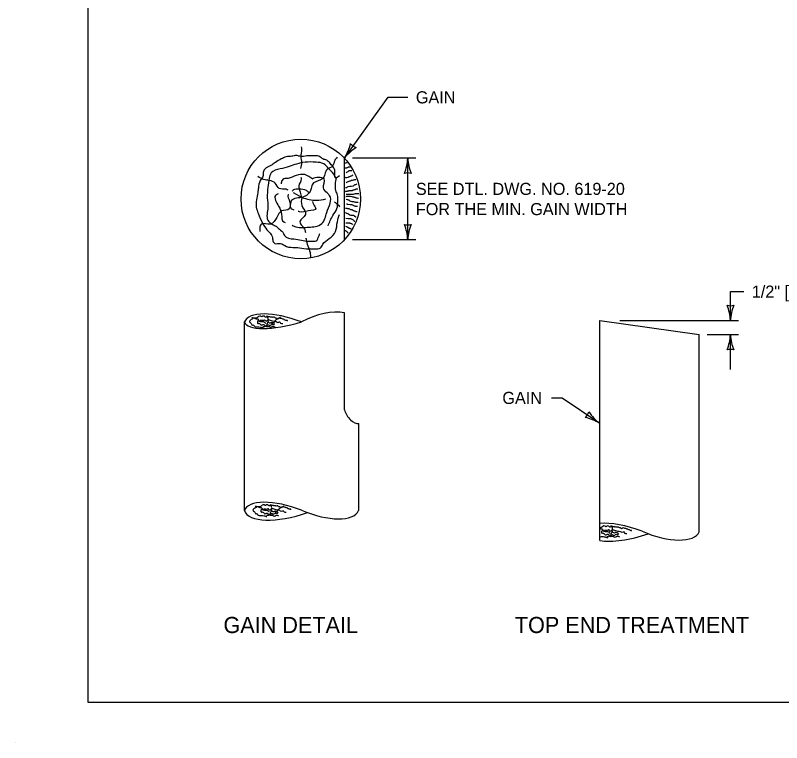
# Model space of a CAD drawing. Extents: x 49991.4 to 50021, y 49987.6 to 50011.4.
# Drawn here: x 49999.977 to 50003.769, y 49999.862 to 50003.463 of the extents above; entities that cross this region are included whole.
import ezdxf

# ---------------------------------------------------------------- set-up
doc = ezdxf.new("R2010")
doc.units = 0
for name, color, linetype in [('Level 1', 7, 'Continuous'), ('Level 2', 7, 'Continuous'), ('Level 3', 7, 'Continuous')]:
    doc.layers.add(name, color=color, linetype=linetype)

msp = doc.modelspace()

# ---------------------------------------------------------------- linework, layer by layer
at = {"layer": 'Level 1'}
for p, q in [((50001.605, 50002.3516), (50001.605, 50002.7561)), ((50001.3944, 50002.561), (50001.3536, 50002.5837)), ((50001.605, 50001.5105), (50001.605, 50001.9906)), ((50002.8687, 50001.9517), (50003.3612, 50001.8825)), ((50002.8687, 50000.8627), (50002.8687, 50001.9517)), ((50001.1101, 50001.011), (50001.1101, 50001.9454)), ((50003.3612, 50000.9062), (50003.3612, 50001.8825)), ((50001.6764, 50001.011), (50001.6764, 50001.4416)), ((49999.9766, 49999.8624), (49999.9766, 49999.8624))]:
    msp.add_line(p, q, dxfattribs=at)
msp.add_lwpolyline([(50008.6146, 50011.2628), (50000.3356, 50011.2628), (50000.3356, 50000.0624), (50008.6146, 50000.0624)], close=True, dxfattribs=at)
for points in [[(50001.6071, 50002.7316), (50001.6092, 50002.7327), (50001.6124, 50002.7327), (50001.6167, 50002.7337), (50001.6188, 50002.7337)], [(50001.6103, 50002.7092), (50001.6113, 50002.7071), (50001.6135, 50002.7081), (50001.6167, 50002.7081), (50001.6188, 50002.7092), (50001.621, 50002.7092), (50001.6231, 50002.7113), (50001.6253, 50002.7124), (50001.6295, 50002.7135), (50001.6338, 50002.7135)], [(50001.6092, 50002.6612), (50001.6113, 50002.6601), (50001.6135, 50002.6601), (50001.6178, 50002.6601), (50001.6231, 50002.6612), (50001.6263, 50002.6633), (50001.6285, 50002.6644), (50001.6306, 50002.6655), (50001.6328, 50002.6655), (50001.6349, 50002.6665), (50001.6381, 50002.6676), (50001.6403, 50002.6687), (50001.6435, 50002.6697), (50001.6445, 50002.6719), (50001.6478, 50002.674)], [(50001.6135, 50002.6836), (50001.6167, 50002.6868), (50001.6199, 50002.6889), (50001.6231, 50002.69), (50001.6253, 50002.6911), (50001.6274, 50002.6932), (50001.6295, 50002.6953), (50001.6328, 50002.6953), (50001.6349, 50002.6953), (50001.637, 50002.6953), (50001.6392, 50002.6953), (50001.6413, 50002.6953)], [(50001.6135, 50002.6345), (50001.6178, 50002.6377), (50001.6199, 50002.6388), (50001.6242, 50002.6409), (50001.6295, 50002.642), (50001.6317, 50002.6431), (50001.6349, 50002.6441), (50001.6381, 50002.6452), (50001.6403, 50002.6463), (50001.6435, 50002.6463), (50001.6456, 50002.6473), (50001.651, 50002.6484), (50001.6542, 50002.6484), (50001.6574, 50002.6495), (50001.6617, 50002.6495)], [(50001.6081, 50002.5919), (50001.6092, 50002.5897), (50001.6103, 50002.5919), (50001.6124, 50002.5929), (50001.6199, 50002.5929), (50001.622, 50002.594), (50001.6242, 50002.594), (50001.6263, 50002.594), (50001.6285, 50002.5951), (50001.6306, 50002.5951), (50001.6328, 50002.5951), (50001.6349, 50002.5951), (50001.637, 50002.5951), (50001.6403, 50002.5951), (50001.6445, 50002.5961), (50001.6467, 50002.5972), (50001.6488, 50002.5983), (50001.6542, 50002.5993), (50001.6563, 50002.6004), (50001.6585, 50002.6015), (50001.6638, 50002.6036), (50001.667, 50002.6047), (50001.6692, 50002.6047), (50001.6713, 50002.6047)], [(50001.6103, 50002.61), (50001.6167, 50002.6111), (50001.6188, 50002.6121), (50001.621, 50002.6143), (50001.6231, 50002.6153), (50001.6317, 50002.6164), (50001.6349, 50002.6175), (50001.637, 50002.6175), (50001.6392, 50002.6175), (50001.6478, 50002.6185), (50001.6499, 50002.6196), (50001.6531, 50002.6228), (50001.6552, 50002.6239), (50001.6585, 50002.6249), (50001.6617, 50002.626), (50001.6649, 50002.6271), (50001.666, 50002.6292)], [(50001.6124, 50002.5663), (50001.6146, 50002.5663), (50001.6167, 50002.5673), (50001.6231, 50002.5673), (50001.6263, 50002.5673), (50001.6285, 50002.5684), (50001.6317, 50002.5684), (50001.6338, 50002.5684), (50001.6424, 50002.5663), (50001.6456, 50002.5652), (50001.6478, 50002.5641), (50001.651, 50002.5641), (50001.6542, 50002.5631), (50001.6563, 50002.562), (50001.6595, 50002.5609), (50001.6617, 50002.5599), (50001.6638, 50002.5599), (50001.667, 50002.5588), (50001.6713, 50002.5577), (50001.6745, 50002.5577)], [(50001.6135, 50002.5769), (50001.6167, 50002.5769), (50001.6188, 50002.5769), (50001.6242, 50002.5769), (50001.6263, 50002.5769), (50001.6317, 50002.5769), (50001.636, 50002.5769), (50001.6381, 50002.5769), (50001.6413, 50002.5769), (50001.6435, 50002.5769), (50001.6456, 50002.5769), (50001.6499, 50002.578), (50001.6606, 50002.5801), (50001.6649, 50002.5801), (50001.6692, 50002.5801), (50001.6713, 50002.5801), (50001.6735, 50002.5801), (50001.6767, 50002.5801)], [(50001.6135, 50002.5535), (50001.6199, 50002.5513), (50001.622, 50002.5503), (50001.6274, 50002.5492), (50001.6295, 50002.5471), (50001.6328, 50002.5449), (50001.637, 50002.5428), (50001.6413, 50002.5417), (50001.6488, 50002.5407), (50001.651, 50002.5407), (50001.6531, 50002.5396), (50001.6552, 50002.5396), (50001.6574, 50002.5396), (50001.6606, 50002.5385), (50001.6649, 50002.5385), (50001.6681, 50002.5385), (50001.6735, 50002.5385)], [(50001.6167, 50002.5321), (50001.6178, 50002.5289), (50001.6199, 50002.5289), (50001.6338, 50002.5268), (50001.6403, 50002.5257), (50001.6435, 50002.5247), (50001.6456, 50002.5247), (50001.6478, 50002.5236), (50001.651, 50002.5215), (50001.6542, 50002.5193), (50001.6574, 50002.5193), (50001.6595, 50002.5183), (50001.6627, 50002.5183), (50001.667, 50002.5183), (50001.6692, 50002.5183)], [(50001.6092, 50002.4863), (50001.6135, 50002.4852), (50001.6156, 50002.4841), (50001.6178, 50002.4841), (50001.622, 50002.482), (50001.6263, 50002.4788), (50001.6295, 50002.4767), (50001.6306, 50002.4745), (50001.6328, 50002.4745), (50001.637, 50002.4735), (50001.6392, 50002.4735), (50001.6413, 50002.4735), (50001.6456, 50002.4735), (50001.6478, 50002.4735), (50001.652, 50002.4724), (50001.6542, 50002.4713), (50001.6542, 50002.4692), (50001.6563, 50002.4681), (50001.6606, 50002.466), (50001.6627, 50002.466)], [(50001.6103, 50002.5087), (50001.6146, 50002.5076), (50001.6178, 50002.5076), (50001.6199, 50002.5065), (50001.6263, 50002.5065), (50001.6306, 50002.5044), (50001.6328, 50002.5033), (50001.6349, 50002.5023), (50001.6424, 50002.5012), (50001.6456, 50002.5001), (50001.651, 50002.4969), (50001.6531, 50002.4959), (50001.6563, 50002.4948), (50001.6595, 50002.4937), (50001.6617, 50002.4916), (50001.6649, 50002.4916), (50001.6681, 50002.4916)], [(50001.6124, 50002.4596), (50001.6253, 50002.4575), (50001.6285, 50002.4575), (50001.6349, 50002.4575), (50001.637, 50002.4564), (50001.6392, 50002.4553), (50001.6413, 50002.4543), (50001.6435, 50002.4532), (50001.6456, 50002.4521), (50001.6478, 50002.45), (50001.651, 50002.4489), (50001.652, 50002.4468), (50001.6542, 50002.4447), (50001.6563, 50002.4436)], [(50001.6113, 50002.4191), (50001.6135, 50002.4169), (50001.6167, 50002.4169), (50001.621, 50002.4148), (50001.6231, 50002.4148), (50001.6242, 50002.4127), (50001.6253, 50002.4105), (50001.6274, 50002.4105), (50001.6295, 50002.4095), (50001.6328, 50002.4095), (50001.6349, 50002.4084), (50001.637, 50002.4084), (50001.6381, 50002.4041)], [(50001.6124, 50002.4361), (50001.6146, 50002.4351), (50001.6274, 50002.4351), (50001.6306, 50002.4351), (50001.6328, 50002.434), (50001.6349, 50002.434), (50001.6403, 50002.4329), (50001.6445, 50002.4297), (50001.6456, 50002.4276)], [(50001.6092, 50002.3999), (50001.6092, 50002.3977), (50001.6124, 50002.3956), (50001.6146, 50002.3945), (50001.6167, 50002.3924), (50001.6188, 50002.3903), (50001.621, 50002.3892), (50001.621, 50002.3871), (50001.6242, 50002.3849)]]:
    msp.add_lwpolyline(points, dxfattribs=at)
msp.add_circle((50001.3894, 50002.5538), 0.2956, dxfattribs=at)
for centre, major_axis, ratio, start_param, end_param in [((50001.4558, 50001.8277), (0.2192, 0.1177), 0.537084, 0.577032, 1.570796), ((50001.3557, 50001.8503), (-0.2457, 0.0951), 0.387082, 4.712389, 6.283185), ((50001.3686, 50002.0242), (-0.2585, -0.0788), 0.304673, 0, 1.570796), ((50001.6514, 50001.5052), (0.036, -0.0602), 0.577668, 4.296437, 6.00385), ((50001.3566, 50000.918), (-0.2457, 0.0951), 0.387082, 4.712389, 6.306248), ((50001.3866, 50001.1087), (-0.2766, -0.0977), 0.384401, 0, 1.563046), ((50001.4354, 50001.1146), (0.2396, -0.1036), 0.420526, 4.719014, 6.283185), ((50003.0413, 50000.8139), (-0.2457, 0.0951), 0.387082, 4.71239, 5.629208), ((50003.0729, 50001.0039), (-0.2766, -0.0977), 0.384401, 0.614947, 1.563386), ((50003.1217, 50001.0098), (0.2396, -0.1036), 0.420526, 4.712389, 6.283185)]:
    msp.add_ellipse(centre, major_axis=major_axis, ratio=ratio, start_param=start_param, end_param=end_param, dxfattribs=at)
for points in [[(50001.3893, 50002.7052), (50001.3944, 50002.7344), (50001.3912, 50002.7628), (50001.3944, 50002.7992), (50001.3928, 50002.8111)], [(50001.5477, 50002.7153), (50001.5324, 50002.7322), (50001.5175, 50002.7459), (50001.4992, 50002.7517), (50001.4842, 50002.7625), (50001.4721, 50002.7668), (50001.4466, 50002.7668), (50001.4194, 50002.7668), (50001.3849, 50002.7651), (50001.3665, 50002.7698), (50001.3454, 50002.7651), (50001.3168, 50002.7625), (50001.2926, 50002.7517), (50001.264, 50002.7351), (50001.2475, 50002.723), (50001.211, 50002.702), (50001.2038, 50002.6856), (50001.202, 50002.6656), (50001.1883, 50002.6445), (50001.1794, 50002.607), (50001.1764, 50002.5857), (50001.169, 50002.5135), (50001.1781, 50002.4832), (50001.2004, 50002.4334), (50001.2218, 50002.4015), (50001.2488, 50002.3653), (50001.2518, 50002.346), (50001.2609, 50002.3338), (50001.2882, 50002.3338), (50001.3184, 50002.3187), (50001.362, 50002.3142), (50001.4043, 50002.3082), (50001.4584, 50002.3067), (50001.4856, 50002.311), (50001.4992, 50002.3306), (50001.5295, 50002.358), (50001.5613, 50002.3926), (50001.5703, 50002.441), (50001.5815, 50002.4767)], [(50001.5692, 50002.76), (50001.5571, 50002.7447), (50001.5466, 50002.7162), (50001.5194, 50002.6996), (50001.5087, 50002.677), (50001.494, 50002.6514), (50001.4877, 50002.6484), (50001.4455, 50002.6244), (50001.4395, 50002.6), (50001.4169, 50002.5713), (50001.3944, 50002.561)], [(50001.5661, 50002.6528), (50001.5526, 50002.677), (50001.5271, 50002.7054), (50001.5028, 50002.7282), (50001.4649, 50002.7358), (50001.4109, 50002.7358), (50001.3687, 50002.7268), (50001.3323, 50002.7145), (50001.287, 50002.7027), (50001.2432, 50002.6829), (50001.2328, 50002.6557), (50001.2265, 50002.6121), (50001.2236, 50002.5592), (50001.2265, 50002.511), (50001.2265, 50002.4489), (50001.245, 50002.4309), (50001.2631, 50002.4205), (50001.2841, 50002.404), (50001.3036, 50002.3827), (50001.3082, 50002.3722), (50001.355, 50002.3557), (50001.3928, 50002.3494), (50001.4258, 50002.345), (50001.4468, 50002.345), (50001.4649, 50002.3467), (50001.4786, 50002.3694), (50001.4836, 50002.383)], [(50001.5815, 50002.6685), (50001.5597, 50002.6582), (50001.5582, 50002.6959), (50001.546, 50002.7171)], [(50001.4484, 50002.6514), (50001.4092, 50002.6742), (50001.3672, 50002.6708), (50001.3263, 50002.6557), (50001.3051, 50002.6528), (50001.2931, 50002.6362), (50001.2926, 50002.6288)], [(50001.3272, 50002.5969), (50001.3172, 50002.6016), (50001.2824, 50002.606), (50001.2631, 50002.6316), (50001.2342, 50002.6452), (50001.2056, 50002.6497), (50001.1769, 50002.6649)], [(50001.3466, 50002.4234), (50001.3653, 50002.4158), (50001.4289, 50002.4144), (50001.462, 50002.4177), (50001.494, 50002.4325), (50001.518, 50002.487), (50001.5314, 50002.5713), (50001.5194, 50002.5834), (50001.5012, 50002.6091), (50001.5043, 50002.6528), (50001.4774, 50002.6605), (50001.4468, 50002.6542)], [(50001.3944, 50002.561), (50001.3881, 50002.588), (50001.3806, 50002.6194), (50001.3928, 50002.6528), (50001.3915, 50002.6598)], [(50001.5246, 50002.4207), (50001.548, 50002.4717), (50001.5678, 50002.5063), (50001.5724, 50002.5443), (50001.5708, 50002.5728), (50001.5633, 50002.5956), (50001.5661, 50002.6589)], [(50001.3471, 50002.5926), (50001.355, 50002.6), (50001.3806, 50002.6044), (50001.4152, 50002.597), (50001.4302, 50002.5863)], [(50001.3944, 50002.561), (50001.34, 50002.5396), (50001.3323, 50002.505), (50001.2946, 50002.4944), (50001.2704, 50002.4627), (50001.2388, 50002.4296), (50001.1937, 50002.4296), (50001.1859, 50002.3934)], [(50001.2774, 50002.58), (50001.2644, 50002.5713), (50001.2796, 50002.5186), (50001.2946, 50002.4777), (50001.3051, 50002.44), (50001.3119, 50002.4375)], [(50001.3566, 50002.4992), (50001.3444, 50002.5035), (50001.337, 50002.5368), (50001.3293, 50002.5758), (50001.33, 50002.5767)], [(50001.3944, 50002.561), (50001.3944, 50002.5215), (50001.4122, 50002.4763), (50001.3854, 50002.4415), (50001.4109, 50002.3978), (50001.4119, 50002.3875)], [(50001.3944, 50002.561), (50001.4682, 50002.5472), (50001.5132, 50002.5542)], [(50001.4476, 50002.5414), (50001.4516, 50002.5275), (50001.4637, 50002.5063), (50001.4275, 50002.4944), (50001.3836, 50002.4898), (50001.3764, 50002.4925)], [(50001.5568, 50002.5395), (50001.5753, 50002.523), (50001.5815, 50002.5143)], [(50001.4148, 50002.3605), (50001.4152, 50002.3557), (50001.4244, 50002.3226), (50001.435, 50002.2892), (50001.4377, 50002.2622)], [(50001.3229, 50001.9486), (50001.3229, 50001.9516), (50001.3171, 50001.9516), (50001.3128, 50001.9544), (50001.3085, 50001.9544), (50001.3042, 50001.9588), (50001.2998, 50001.9588), (50001.294, 50001.9616), (50001.2897, 50001.9616), (50001.2811, 50001.9645), (50001.2724, 50001.9602), (50001.2681, 50001.9645), (50001.2624, 50001.9645), (50001.258, 50001.9688), (50001.2508, 50001.9674), (50001.2465, 50001.9688), (50001.2421, 50001.9688), (50001.2364, 50001.9703), (50001.2321, 50001.9703), (50001.2263, 50001.9717), (50001.2191, 50001.9717), (50001.2191, 50001.9688), (50001.2148, 50001.9688), (50001.209, 50001.9731), (50001.2004, 50001.9731), (50001.196, 50001.9703), (50001.1917, 50001.9731), (50001.1802, 50001.9717), (50001.1701, 50001.9645), (50001.1586, 50001.9645), (50001.1528, 50001.9631), (50001.1485, 50001.9588), (50001.1398, 50001.9544), (50001.1355, 50001.9472), (50001.1369, 50001.9443), (50001.1441, 50001.9371), (50001.1499, 50001.9285), (50001.1528, 50001.9313), (50001.1586, 50001.9256), (50001.1658, 50001.9213), (50001.1744, 50001.9213), (50001.1903, 50001.9198), (50001.2046, 50001.9155)], [(50001.2162, 50001.9371), (50001.2104, 50001.9429), (50001.1989, 50001.9458), (50001.1859, 50001.9472), (50001.1773, 50001.9588), (50001.1715, 50001.9588), (50001.1672, 50001.9602), (50001.1571, 50001.9645), (50001.147, 50001.966)], [(50001.2998, 50001.9357), (50001.2912, 50001.9371), (50001.2854, 50001.9443), (50001.2767, 50001.9415), (50001.2681, 50001.9458), (50001.2552, 50001.9472), (50001.245, 50001.9501), (50001.2249, 50001.9516), (50001.2162, 50001.9472), (50001.2119, 50001.9544), (50001.2061, 50001.953), (50001.1975, 50001.9516), (50001.1888, 50001.9516), (50001.1874, 50001.9472), (50001.1816, 50001.9501), (50001.1773, 50001.9501), (50001.1744, 50001.9415), (50001.1773, 50001.9371), (50001.1816, 50001.9386), (50001.1874, 50001.9357), (50001.1931, 50001.9299), (50001.2061, 50001.9328), (50001.2148, 50001.9242), (50001.2263, 50001.9227), (50001.2321, 50001.9227), (50001.2407, 50001.9184), (50001.2494, 50001.9227), (50001.2624, 50001.9198)], [(50001.2306, 50001.9429), (50001.2263, 50001.953), (50001.2291, 50001.9602), (50001.2249, 50001.9688), (50001.222, 50001.9761)], [(50001.245, 50001.9371), (50001.2624, 50001.9501), (50001.2681, 50001.9573), (50001.2825, 50001.9645), (50001.2883, 50001.9703)], [(50001.2205, 50001.927), (50001.2104, 50001.9213), (50001.2018, 50001.9213)], [(50001.2566, 50001.9386), (50001.2508, 50001.94), (50001.2407, 50001.9415), (50001.2379, 50001.9386), (50001.2321, 50001.9415), (50001.2249, 50001.9415), (50001.222, 50001.927), (50001.2277, 50001.9313), (50001.2321, 50001.9285), (50001.2393, 50001.9285), (50001.2465, 50001.9328), (50001.2552, 50001.9313), (50001.258, 50001.9343), (50001.2594, 50001.9371)], [(50001.3402, 50001.0146), (50001.3402, 50001.0175), (50001.3344, 50001.0175), (50001.3302, 50001.0204), (50001.3258, 50001.0204), (50001.3215, 50001.0247), (50001.3172, 50001.0247), (50001.3114, 50001.0276), (50001.3071, 50001.0276), (50001.2984, 50001.0304), (50001.2898, 50001.0261), (50001.2854, 50001.0304), (50001.2797, 50001.0304), (50001.2754, 50001.0348), (50001.2681, 50001.0334), (50001.2639, 50001.0348), (50001.2595, 50001.0348), (50001.2537, 50001.0362), (50001.2494, 50001.0362), (50001.2436, 50001.0376), (50001.2364, 50001.0376), (50001.2364, 50001.0348), (50001.2321, 50001.0348), (50001.2264, 50001.0391), (50001.2177, 50001.0391), (50001.2134, 50001.0362), (50001.2091, 50001.0391), (50001.1976, 50001.0376), (50001.1874, 50001.0304), (50001.1759, 50001.0304), (50001.1701, 50001.029), (50001.1658, 50001.0247), (50001.1572, 50001.0204), (50001.1528, 50001.0131), (50001.1543, 50001.0103), (50001.1615, 50001.0031), (50001.1673, 50000.9944), (50001.1701, 50000.9973), (50001.1759, 50000.9916), (50001.1831, 50000.9872), (50001.1918, 50000.9872), (50001.2076, 50000.9858), (50001.222, 50000.9814)], [(50001.248, 50001.0089), (50001.2436, 50001.0189), (50001.2465, 50001.0261), (50001.2422, 50001.0348), (50001.2394, 50001.042)], [(50001.2336, 50001.0031), (50001.2278, 50001.0089), (50001.2163, 50001.0117), (50001.2033, 50001.0131), (50001.1946, 50001.0247), (50001.1888, 50001.0247), (50001.1846, 50001.0261), (50001.1745, 50001.0304), (50001.1643, 50001.0319)], [(50001.3172, 50001.0016), (50001.3085, 50001.0031), (50001.3027, 50001.0103), (50001.2941, 50001.0074), (50001.2854, 50001.0117), (50001.2725, 50001.0131), (50001.2624, 50001.0161), (50001.2422, 50001.0175), (50001.2336, 50001.0131), (50001.2292, 50001.0204), (50001.2235, 50001.0189), (50001.2148, 50001.0175), (50001.2062, 50001.0175), (50001.2047, 50001.0131), (50001.199, 50001.0161), (50001.1946, 50001.0161), (50001.1918, 50001.0074), (50001.1946, 50001.0031), (50001.199, 50001.0045), (50001.2047, 50001.0016), (50001.2105, 50000.9959), (50001.2235, 50000.9988), (50001.2321, 50000.9901), (50001.2436, 50000.9886), (50001.2494, 50000.9886), (50001.2581, 50000.9843), (50001.2667, 50000.9886), (50001.2797, 50000.9858)], [(50001.2739, 50001.0045), (50001.2681, 50001.0059), (50001.2581, 50001.0074), (50001.2552, 50001.0045), (50001.2494, 50001.0074), (50001.2422, 50001.0074), (50001.2394, 50000.993), (50001.2451, 50000.9973), (50001.2494, 50000.9944), (50001.2566, 50000.9944), (50001.2639, 50000.9988), (50001.2725, 50000.9973), (50001.2754, 50001.0002), (50001.2768, 50001.0031)], [(50001.2624, 50001.0031), (50001.2797, 50001.0161), (50001.2854, 50001.0233), (50001.2999, 50001.0304), (50001.3057, 50001.0362)], [(50001.2379, 50000.993), (50001.2278, 50000.9872), (50001.2191, 50000.9872)], [(50003.0265, 50000.9098), (50003.0265, 50000.9127), (50003.0207, 50000.9127), (50003.0164, 50000.9156), (50003.0121, 50000.9156), (50003.0078, 50000.9199), (50003.0034, 50000.9199), (50002.9976, 50000.9228), (50002.9933, 50000.9228), (50002.9847, 50000.9257), (50002.9761, 50000.9214), (50002.9717, 50000.9257), (50002.966, 50000.9257), (50002.9616, 50000.93), (50002.9544, 50000.9286), (50002.9501, 50000.93), (50002.9458, 50000.93), (50002.94, 50000.9314), (50002.9357, 50000.9314), (50002.9299, 50000.9329), (50002.9227, 50000.9329), (50002.9227, 50000.93), (50002.9184, 50000.93), (50002.9126, 50000.9343), (50002.904, 50000.9343), (50002.8996, 50000.9314), (50002.8953, 50000.9343), (50002.8838, 50000.9329), (50002.8737, 50000.9257), (50002.8687, 50000.9257)], [(50002.9343, 50000.9041), (50002.9299, 50000.9142), (50002.9328, 50000.9214), (50002.9285, 50000.93), (50002.9256, 50000.9372)], [(50002.9198, 50000.8983), (50002.914, 50000.9041), (50002.9025, 50000.9069), (50002.8895, 50000.9084), (50002.8809, 50000.9199), (50002.8751, 50000.9199), (50002.8708, 50000.9214), (50002.8687, 50000.9222)], [(50003.0034, 50000.8969), (50002.9948, 50000.8983), (50002.989, 50000.9055), (50002.9803, 50000.9027), (50002.9717, 50000.9069), (50002.9588, 50000.9084), (50002.9486, 50000.9113), (50002.9285, 50000.9127), (50002.9198, 50000.9084), (50002.9155, 50000.9156), (50002.9098, 50000.9142), (50002.9011, 50000.9127), (50002.8925, 50000.9127), (50002.891, 50000.9084), (50002.8853, 50000.9113), (50002.8809, 50000.9113), (50002.878, 50000.9027), (50002.8809, 50000.8983), (50002.8853, 50000.8997), (50002.891, 50000.8969), (50002.8968, 50000.8911), (50002.9098, 50000.894), (50002.9184, 50000.8854), (50002.9299, 50000.8839), (50002.9357, 50000.8839), (50002.9443, 50000.8796), (50002.953, 50000.8839), (50002.966, 50000.881)], [(50002.9241, 50000.8882), (50002.914, 50000.8824), (50002.9054, 50000.8824)], [(50002.9602, 50000.8997), (50002.9544, 50000.9012), (50002.9443, 50000.9027), (50002.9415, 50000.8997), (50002.9357, 50000.9027), (50002.9285, 50000.9027), (50002.9256, 50000.8882), (50002.9313, 50000.8925), (50002.9357, 50000.8897), (50002.9429, 50000.8897), (50002.9501, 50000.894), (50002.9588, 50000.8925), (50002.9616, 50000.8954), (50002.9631, 50000.8983)], [(50002.8687, 50000.8828), (50002.8694, 50000.8824), (50002.878, 50000.8824), (50002.8939, 50000.881), (50002.9083, 50000.8767)]]:
    msp.add_spline(points, degree=3, dxfattribs=at)
at = {"layer": 'Level 3'}
for p, q in [((50001.605, 50002.7561), (50001.8223, 50003.057)), ((50001.8223, 50003.057), (50001.9187, 50003.057)), ((50001.9587, 50002.7561), (50001.645, 50002.7561)), ((50001.9187, 50002.3516), (50001.9187, 50002.7561)), ((50001.9587, 50002.3516), (50001.645, 50002.3516)), ((50003.5156, 50001.9517), (50003.5156, 50002.0951)), ((50003.5156, 50002.0951), (50003.5813, 50002.0951)), ((50002.9687, 50001.9517), (50003.5556, 50001.9517)), ((50003.4012, 50001.8825), (50003.5556, 50001.8825)), ((50003.5156, 50001.7091), (50003.5156, 50001.8825)), ((50002.6299, 50001.569), (50002.6837, 50001.569)), ((50002.6837, 50001.569), (50002.8687, 50001.4435))]:
    msp.add_line(p, q, dxfattribs=at)
for centre, radius, start, end in [((50001.4195, 50002.8787), 0.2223, 326.5292, 346.7127), ((50001.6801, 50002.86), 0.0548, 216.3076, 252.0299), ((50001.7869, 50002.6105), 0.233, 122.0916, 141.3414), ((50001.686, 50002.7676), 0.233, 337.9228, 357.1727), ((50002.1408, 50002.7652), 0.2223, 182.3605, 202.544), ((50001.9187, 50002.6279), 0.0548, 72.1388, 107.8612), ((50001.6966, 50002.3424), 0.2223, 2.3605, 22.544), ((50001.9187, 50002.4798), 0.0548, 252.1388, 287.8612), ((50002.1514, 50002.3401), 0.233, 157.9228, 177.1727), ((50003.5156, 50002.0799), 0.0548, 252.1388, 287.8612), ((50003.2829, 50001.9402), 0.233, 2.8273, 22.0772), ((50003.7377, 50001.9425), 0.2223, 157.456, 177.6395), ((50003.2935, 50001.8917), 0.2223, 337.456, 357.6395), ((50003.7483, 50001.894), 0.233, 182.8273, 202.0772), ((50003.5156, 50001.7543), 0.0548, 72.1388, 107.8612), ((50002.7626, 50001.5155), 0.0548, 307.9855, 343.7079), ((50003.001, 50001.6222), 0.2223, 213.3027, 233.4862), ((50002.7476, 50001.2445), 0.233, 58.674, 77.9238)]:
    msp.add_arc(centre, radius, start, end, dxfattribs=at)

# ---------------------------------------------------------------- texts
at = {"layer": 'Level 2'}
for s, height, p in [('GAIN', 0.06, (50001.9587, 50003.027)), ('SEE DTL. DWG. NO. 619-20', 0.06, (50001.9587, 50002.5738)), ('FOR THE MIN. GAIN WIDTH', 0.06, (50001.9587, 50002.4738)), ('1/2" [12.5] CHAMFER', 0.06, (50003.6213, 50002.0651)), ('GAIN', 0.06, (50002.3869, 50001.539)), ('GAIN DETAIL', 0.08, (50001.0067, 50000.405)), ('TOP END TREATMENT', 0.08, (50002.4488, 50000.405))]:
    msp.add_text(s, height=height, dxfattribs=at).set_placement(p)

doc.saveas('drawing.dxf')
